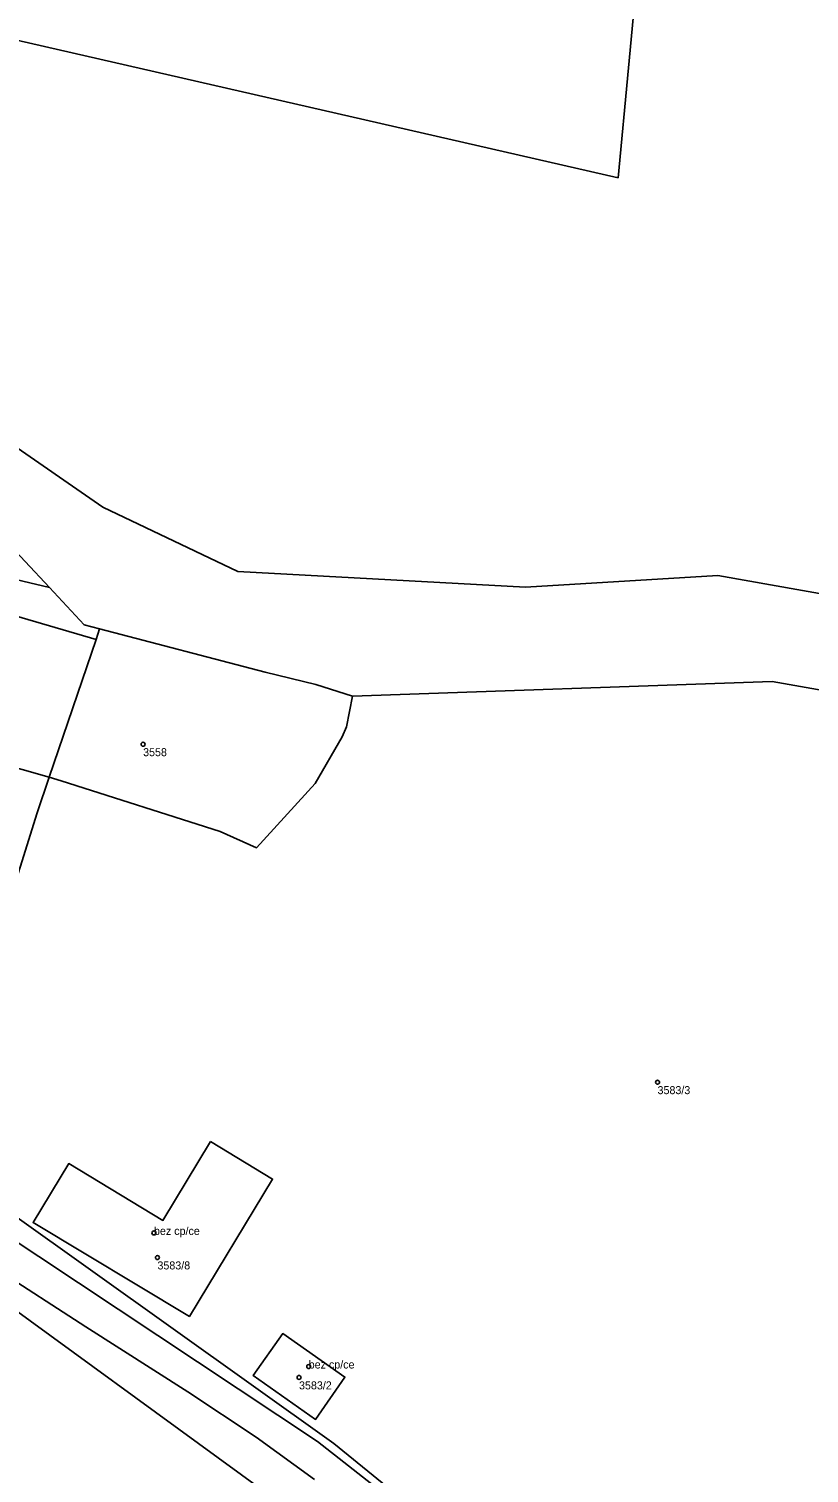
# Model space of a CAD drawing. Extents: x -878211 to -870363, y -1058464 to -1052522.
# Drawn here: x -876091.8 to -875994.4, y -1055083.2 to -1054902.7 of the extents above; entities that cross this region are included whole.
import ezdxf

# ---------------------------------------------------------------- set-up
doc = ezdxf.new("R2010")
doc.units = 0
for name, color, linetype in [('Vrstva 50', 7, 'Continuous'), ('Vrstva 51', 7, 'Continuous'), ('Vrstva 52', 7, 'Continuous')]:
    doc.layers.add(name, color=color, linetype=linetype)

msp = doc.modelspace()

# ---------------------------------------------------------------- linework, layer by layer
at = {"layer": 'Vrstva 50'}
for centre in [(-876077.56, -1054992.12994), (-876013.29, -1055034.35994), (-876076.2, -1055053.18994), (-876075.77, -1055056.25994), (-876056.87, -1055069.87994), (-876058.08, -1055071.24994)]:
    msp.add_circle(centre, 0.25, dxfattribs=at)
at = {"layer": 'Vrstva 51'}
for points in [[(-875974.99, -1054901.41), (-876001.72, -1054892.47), (-876015.02, -1054891.04), (-876015.64, -1054893.83), (-876018.23, -1054921.34), (-876125.04, -1054896.88), (-876134.69, -1054888.76), (-876137.52, -1054886.38), (-876144.48, -1054886.15), (-876152.96, -1054886.86), (-876157.37, -1054888.23), (-876173.39, -1054897.42), (-876157.48, -1054901.46), (-876146.13, -1054907.97), (-876126.77, -1054921.27), (-876094.91, -1054953.97), (-876082.57, -1054962.49), (-876065.74, -1054970.53), (-876029.77, -1054972.51), (-876005.75, -1054971.06), (-875977.32, -1054976.08)], [(-875977.32, -1054976.08), (-876005.75, -1054971.06), (-876029.77, -1054972.51), (-876065.74, -1054970.53), (-876082.57, -1054962.49), (-876094.91, -1054953.97), (-876126.77, -1054921.27), (-876146.13, -1054907.97), (-876157.48, -1054901.46), (-876173.39, -1054897.42), (-876178.26, -1054895.56), (-876195.87, -1054888.11), (-876204.52, -1054889.32), (-876212.02, -1054889.19), (-876283, -1054897.41)], [(-876262.86, -1054909.66), (-876243.34, -1054905.33), (-876202.42, -1054903.37), (-876182.41, -1054909.92), (-876177.39, -1054910.96), (-876155.83, -1054918.33), (-876139.66, -1054928.98), (-876127.99, -1054935.55), (-876114.13, -1054948.72), (-876095.32, -1054966.04), (-876089.25, -1054972.56), (-876084.93, -1054977.21), (-876082.99, -1054977.72), (-876062.33, -1054983.11), (-876055.99, -1054984.68), (-876051.39, -1054986.14), (-875998.96, -1054984.29), (-875978.7, -1054987.87), (-875906.55, -1055032.87), (-875902.45, -1055033.95), (-875848.87, -1055050.05), (-875834.65, -1055076.69), (-875824, -1055089.28), (-875807.56, -1055091.63)], [(-876094.37, -1054975.83), (-876083.43, -1054979.02), (-876082.99, -1054977.72), (-876084.93, -1054977.21), (-876089.25, -1054972.56), (-876109.46, -1054967.74)], [(-876034.65, -1055095.81), (-876055.78, -1055079.24), (-876105.63, -1055046.16), (-876111.06, -1055042.43), (-876126.23, -1055029.14), (-876137.56, -1055018.26), (-876146.41, -1055010.04), (-876156.39, -1055001.61), (-876158.32, -1054999.97), (-876160.15, -1055011.62), (-876125.07, -1055037.07), (-876115.97, -1055043.68), (-876114.28, -1055045.66), (-876107.77, -1055049.92), (-876096.22, -1055057.5), (-876084.72, -1055064.92), (-876071.96, -1055073.05), (-876063.43, -1055078.72), (-876056.15, -1055083.98)], [(-876056.15, -1055083.98), (-876063.43, -1055078.72), (-876071.96, -1055073.05), (-876084.72, -1055064.92), (-876096.22, -1055057.5), (-876107.77, -1055049.92), (-876114.28, -1055045.66), (-876112.89, -1055047.29), (-876109.68, -1055051.07), (-876107.35, -1055052.74), (-876054.99, -1055090.93)]]:
    msp.add_lwpolyline(points, dxfattribs=at)
for points in [[(-876018.23, -1054921.34), (-876015.64, -1054893.83), (-876041.82, -1054886.07), (-876083.69, -1054888.22), (-876133.26, -1054888.74), (-876134.69, -1054888.76), (-876125.04, -1054896.88)], [(-876108.33, -1054963.38), (-876109.46, -1054967.74), (-876089.25, -1054972.56), (-876095.32, -1054966.04), (-876105.15, -1054964.03)], [(-876089.29, -1054996.25), (-876083.43, -1054979.02), (-876094.37, -1054975.83), (-876099.15, -1054993.44)], [(-876056.06, -1054997.03), (-876052.67, -1054991.22), (-876052.15, -1054989.95), (-876051.39, -1054986.14), (-876055.99, -1054984.68), (-876062.33, -1054983.11), (-876082.99, -1054977.72), (-876083.43, -1054979.02), (-876089.29, -1054996.25), (-876087.78, -1054996.68), (-876067.92, -1055003.02), (-876063.41, -1055005.05)], [(-876097.42, -1055021.74), (-876104.26, -1055043.49), (-876053.74, -1055079.5), (-876016.38, -1055109.9), (-875979.71, -1055134.31), (-875976.33, -1055133.07), (-875966.79, -1055136.01), (-875949.8, -1055118.58), (-875906.55, -1055032.87), (-875978.7, -1054987.87), (-875998.96, -1054984.29), (-876051.39, -1054986.14), (-876052.15, -1054989.95), (-876052.67, -1054991.22), (-876056.06, -1054997.03), (-876063.41, -1055005.05), (-876067.92, -1055003.02), (-876087.78, -1054996.68), (-876089.29, -1054996.25), (-876090.8, -1055000.71)], [(-876116, -1055002.47), (-876119.47, -1055012.84), (-876097.42, -1055021.74), (-876090.8, -1055000.71), (-876089.29, -1054996.25), (-876099.15, -1054993.44), (-876111.07, -1054987.72), (-876111.46, -1054988.9), (-876105.35, -1054991.65), (-876107.42, -1054996.21), (-876106.73, -1054996.52), (-876106.08, -1054998.16), (-876106.81, -1054999.76), (-876108.47, -1055000.38), (-876109.15, -1055000.07), (-876111.23, -1055004.61)], [(-876069.14, -1055041.78), (-876061.39, -1055046.47), (-876071.77, -1055063.61), (-876091.31, -1055051.9), (-876086.84, -1055044.52), (-876075.09, -1055051.62)], [(-876069.14, -1055041.78), (-876075.09, -1055051.62), (-876086.84, -1055044.52), (-876091.31, -1055051.9), (-876071.77, -1055063.61), (-876061.39, -1055046.47)], [(-875977.58, -1055142.97), (-875979.71, -1055134.31), (-876016.38, -1055109.9), (-876053.74, -1055079.5), (-876104.26, -1055043.49), (-876105.63, -1055046.16), (-876055.78, -1055079.24), (-876034.65, -1055095.81), (-875993.71, -1055132)], [(-876026.71, -1055116.15), (-876054.99, -1055090.93), (-876107.35, -1055052.74), (-876117.61, -1055074.46), (-876096.34, -1055109.09), (-876070.12, -1055147.03), (-876039.02, -1055184.03), (-875996.85, -1055230.09), (-875978.11, -1055212.67), (-875964.02, -1055196.27), (-875956.01, -1055187.77), (-875992.23, -1055151.65), (-876009.21, -1055134.73)], [(-876052.34, -1055071.21), (-876060.11, -1055065.77), (-876063.8, -1055071.01), (-876056.02, -1055076.48)], [(-876052.34, -1055071.21), (-876056.02, -1055076.48), (-876063.8, -1055071.01), (-876060.11, -1055065.77)]]:
    msp.add_lwpolyline(points, close=True, dxfattribs=at)
at = {"layer": 'Vrstva 52'}
for points in [[(-876069.14, -1055041.78), (-876075.09, -1055051.62), (-876086.84, -1055044.52), (-876091.31, -1055051.9), (-876071.77, -1055063.61), (-876061.39, -1055046.47)], [(-876063.8, -1055071.01), (-876056.02, -1055076.48), (-876052.34, -1055071.21), (-876060.11, -1055065.77)]]:
    msp.add_lwpolyline(points, close=True, dxfattribs=at)

# ---------------------------------------------------------------- texts
at = {"layer": 'Vrstva 50'}
for s, p in [('3558', (-876077.56, -1054993.619)), ('3583/3', (-876013.29, -1055035.849)), ('bez cp/ce', (-876076.2, -1055053.44)), ('3583/8', (-876075.77, -1055057.749)), ('bez cp/ce', (-876056.87, -1055070.129)), ('3583/2', (-876058.08, -1055072.739))]:
    msp.add_text(s, height=0.999996, dxfattribs=at).set_placement(p)

doc.saveas('drawing.dxf')
